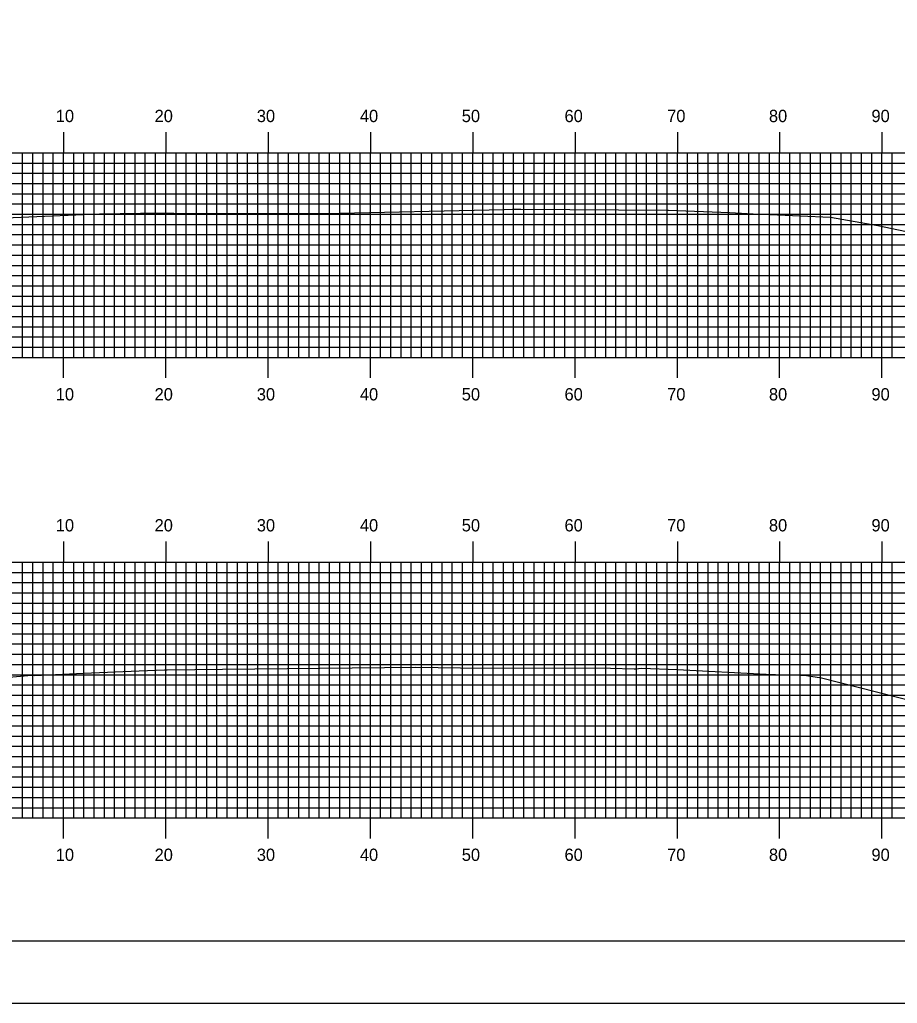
# Model space of a CAD drawing. Extents: x 855074 to 855418, y 366605 to 366825.
# Drawn here: x 855245.8 to 855331.6, y 366604.9 to 366701.1 of the extents above; entities that cross this region are included whole.
import ezdxf

# ---------------------------------------------------------------- set-up
doc = ezdxf.new("R2010")
doc.units = 0
for name, color, linetype in [('BORDER', 7, 'Continuous'), ('H_V ANNOTATION', 7, 'Continuous'), ('M_Roadway_Centerline', 7, 'Continuous'), ('MAJOR', 7, 'Continuous'), ('MINOR', 7, 'Continuous'), ('PLOT BOUNDARY', 7, 'Continuous'), ('S_Roadway_Centerline', 7, 'Continuous')]:
    doc.layers.add(name, color=color, linetype=linetype)

msp = doc.modelspace()

# ---------------------------------------------------------------- linework, layer by layer
at = {"layer": 'BORDER'}
msp.add_lwpolyline([(855090.469, 366611.055), (855410.469, 366611.055), (855410.469, 366821.055), (855090.469, 366821.055)], close=True, dxfattribs=at)
at = {"layer": 'MAJOR'}
for p, q in [((855250.069, 366690.059), (855250.069, 366688.055)), ((855260.069, 366690.059), (855260.069, 366688.055)), ((855270.069, 366690.059), (855270.069, 366688.055)), ((855280.069, 366690.059), (855280.069, 366688.055)), ((855290.069, 366690.059), (855290.069, 366688.055)), ((855300.069, 366690.059), (855300.069, 366688.055)), ((855310.069, 366690.059), (855310.069, 366688.055)), ((855320.069, 366690.059), (855320.069, 366688.055)), ((855330.069, 366690.059), (855330.069, 366688.055)), ((855100.069, 366688.055), (855380.069, 366688.055)), ((855100.069, 366688.055), (855380.069, 366688.055)), ((855250.069, 366668.055), (855250.069, 366688.055)), ((855260.069, 366668.055), (855260.069, 366688.055)), ((855270.069, 366668.055), (855270.069, 366688.055)), ((855280.069, 366668.055), (855280.069, 366688.055)), ((855290.069, 366668.055), (855290.069, 366688.055)), ((855300.069, 366668.055), (855300.069, 366688.055)), ((855310.069, 366668.055), (855310.069, 366688.055)), ((855320.069, 366668.055), (855320.069, 366688.055)), ((855330.069, 366668.055), (855330.069, 366688.055)), ((855100.069, 366683.055), (855380.069, 366683.055)), ((855100.069, 366678.055), (855380.069, 366678.055)), ((855100.069, 366673.055), (855380.069, 366673.055)), ((855100.069, 366668.055), (855380.069, 366668.055)), ((855100.069, 366668.055), (855380.069, 366668.055)), ((855250.069, 366666.051), (855250.069, 366668.055)), ((855260.069, 366666.051), (855260.069, 366668.055)), ((855270.069, 366666.051), (855270.069, 366668.055)), ((855280.069, 366666.051), (855280.069, 366668.055)), ((855290.069, 366666.051), (855290.069, 366668.055)), ((855300.069, 366666.051), (855300.069, 366668.055)), ((855310.069, 366666.051), (855310.069, 366668.055)), ((855320.069, 366666.051), (855320.069, 366668.055)), ((855330.069, 366666.051), (855330.069, 366668.055)), ((855250.069, 366650.059), (855250.069, 366648.055)), ((855260.069, 366650.059), (855260.069, 366648.055)), ((855270.069, 366650.059), (855270.069, 366648.055)), ((855280.069, 366650.059), (855280.069, 366648.055)), ((855290.069, 366650.059), (855290.069, 366648.055)), ((855300.069, 366650.059), (855300.069, 366648.055)), ((855310.069, 366650.059), (855310.069, 366648.055)), ((855320.069, 366650.059), (855320.069, 366648.055)), ((855330.069, 366650.059), (855330.069, 366648.055)), ((855100.069, 366648.055), (855380.069, 366648.055)), ((855100.069, 366648.055), (855380.069, 366648.055)), ((855250.069, 366623.055), (855250.069, 366648.055)), ((855260.069, 366623.055), (855260.069, 366648.055)), ((855270.069, 366623.055), (855270.069, 366648.055)), ((855280.069, 366623.055), (855280.069, 366648.055)), ((855290.069, 366623.055), (855290.069, 366648.055)), ((855300.069, 366623.055), (855300.069, 366648.055)), ((855310.069, 366623.055), (855310.069, 366648.055)), ((855320.069, 366623.055), (855320.069, 366648.055)), ((855330.069, 366623.055), (855330.069, 366648.055)), ((855100.069, 366643.055), (855380.069, 366643.055)), ((855100.069, 366638.055), (855380.069, 366638.055)), ((855100.069, 366633.055), (855380.069, 366633.055)), ((855100.069, 366628.055), (855380.069, 366628.055)), ((855100.069, 366623.055), (855380.069, 366623.055)), ((855100.069, 366623.055), (855380.069, 366623.055)), ((855250.069, 366621.051), (855250.069, 366623.055)), ((855260.069, 366621.051), (855260.069, 366623.055)), ((855270.069, 366621.051), (855270.069, 366623.055)), ((855280.069, 366621.051), (855280.069, 366623.055)), ((855290.069, 366621.051), (855290.069, 366623.055)), ((855300.069, 366621.051), (855300.069, 366623.055)), ((855310.069, 366621.051), (855310.069, 366623.055)), ((855320.069, 366621.051), (855320.069, 366623.055)), ((855330.069, 366621.051), (855330.069, 366623.055))]:
    msp.add_line(p, q, dxfattribs=at)
at = {"layer": 'MINOR'}
for p, q in [((855246.069, 366668.055), (855246.069, 366688.055)), ((855247.069, 366668.055), (855247.069, 366688.055)), ((855248.069, 366668.055), (855248.069, 366688.055)), ((855249.069, 366668.055), (855249.069, 366688.055)), ((855251.069, 366668.055), (855251.069, 366688.055)), ((855252.069, 366668.055), (855252.069, 366688.055)), ((855253.069, 366668.055), (855253.069, 366688.055)), ((855254.069, 366668.055), (855254.069, 366688.055)), ((855255.069, 366668.055), (855255.069, 366688.055)), ((855256.069, 366668.055), (855256.069, 366688.055)), ((855257.069, 366668.055), (855257.069, 366688.055)), ((855258.069, 366668.055), (855258.069, 366688.055)), ((855259.069, 366668.055), (855259.069, 366688.055)), ((855261.069, 366668.055), (855261.069, 366688.055)), ((855262.069, 366668.055), (855262.069, 366688.055)), ((855263.069, 366668.055), (855263.069, 366688.055)), ((855264.069, 366668.055), (855264.069, 366688.055)), ((855265.069, 366668.055), (855265.069, 366688.055)), ((855266.069, 366668.055), (855266.069, 366688.055)), ((855267.069, 366668.055), (855267.069, 366688.055)), ((855268.069, 366668.055), (855268.069, 366688.055)), ((855269.069, 366668.055), (855269.069, 366688.055)), ((855271.069, 366668.055), (855271.069, 366688.055)), ((855272.069, 366668.055), (855272.069, 366688.055)), ((855273.069, 366668.055), (855273.069, 366688.055)), ((855274.069, 366668.055), (855274.069, 366688.055)), ((855275.069, 366668.055), (855275.069, 366688.055)), ((855276.069, 366668.055), (855276.069, 366688.055)), ((855277.069, 366668.055), (855277.069, 366688.055)), ((855278.069, 366668.055), (855278.069, 366688.055)), ((855279.069, 366668.055), (855279.069, 366688.055)), ((855281.069, 366668.055), (855281.069, 366688.055)), ((855282.069, 366668.055), (855282.069, 366688.055)), ((855283.069, 366668.055), (855283.069, 366688.055)), ((855284.069, 366668.055), (855284.069, 366688.055)), ((855285.069, 366668.055), (855285.069, 366688.055)), ((855286.069, 366668.055), (855286.069, 366688.055)), ((855287.069, 366668.055), (855287.069, 366688.055)), ((855288.069, 366668.055), (855288.069, 366688.055)), ((855289.069, 366668.055), (855289.069, 366688.055)), ((855291.069, 366668.055), (855291.069, 366688.055)), ((855292.069, 366668.055), (855292.069, 366688.055)), ((855293.069, 366668.055), (855293.069, 366688.055)), ((855294.069, 366668.055), (855294.069, 366688.055)), ((855295.069, 366668.055), (855295.069, 366688.055)), ((855296.069, 366668.055), (855296.069, 366688.055)), ((855297.069, 366668.055), (855297.069, 366688.055)), ((855298.069, 366668.055), (855298.069, 366688.055)), ((855299.069, 366668.055), (855299.069, 366688.055)), ((855301.069, 366668.055), (855301.069, 366688.055)), ((855302.069, 366668.055), (855302.069, 366688.055)), ((855303.069, 366668.055), (855303.069, 366688.055)), ((855304.069, 366668.055), (855304.069, 366688.055)), ((855305.069, 366668.055), (855305.069, 366688.055)), ((855306.069, 366668.055), (855306.069, 366688.055)), ((855307.069, 366668.055), (855307.069, 366688.055)), ((855308.069, 366668.055), (855308.069, 366688.055)), ((855309.069, 366668.055), (855309.069, 366688.055)), ((855311.069, 366668.055), (855311.069, 366688.055)), ((855312.069, 366668.055), (855312.069, 366688.055)), ((855313.069, 366668.055), (855313.069, 366688.055)), ((855314.069, 366668.055), (855314.069, 366688.055)), ((855315.069, 366668.055), (855315.069, 366688.055)), ((855316.069, 366668.055), (855316.069, 366688.055)), ((855317.069, 366668.055), (855317.069, 366688.055)), ((855318.069, 366668.055), (855318.069, 366688.055)), ((855319.069, 366668.055), (855319.069, 366688.055)), ((855321.069, 366668.055), (855321.069, 366688.055)), ((855322.069, 366668.055), (855322.069, 366688.055)), ((855323.069, 366668.055), (855323.069, 366688.055)), ((855324.069, 366668.055), (855324.069, 366688.055)), ((855325.069, 366668.055), (855325.069, 366688.055)), ((855326.069, 366668.055), (855326.069, 366688.055)), ((855327.069, 366668.055), (855327.069, 366688.055)), ((855328.069, 366668.055), (855328.069, 366688.055)), ((855329.069, 366668.055), (855329.069, 366688.055)), ((855331.069, 366668.055), (855331.069, 366688.055)), ((855100.069, 366687.055), (855380.069, 366687.055)), ((855100.069, 366686.055), (855380.069, 366686.055)), ((855100.069, 366685.055), (855380.069, 366685.055)), ((855100.069, 366684.055), (855380.069, 366684.055)), ((855100.069, 366682.055), (855380.069, 366682.055)), ((855100.069, 366681.055), (855380.069, 366681.055)), ((855100.069, 366680.055), (855380.069, 366680.055)), ((855100.069, 366679.055), (855380.069, 366679.055)), ((855100.069, 366677.055), (855380.069, 366677.055)), ((855100.069, 366676.055), (855380.069, 366676.055)), ((855100.069, 366675.055), (855380.069, 366675.055)), ((855100.069, 366674.055), (855380.069, 366674.055)), ((855100.069, 366672.055), (855380.069, 366672.055)), ((855100.069, 366671.055), (855380.069, 366671.055)), ((855100.069, 366670.055), (855380.069, 366670.055)), ((855100.069, 366669.055), (855380.069, 366669.055)), ((855246.069, 366623.055), (855246.069, 366648.055)), ((855247.069, 366623.055), (855247.069, 366648.055)), ((855248.069, 366623.055), (855248.069, 366648.055)), ((855249.069, 366623.055), (855249.069, 366648.055)), ((855251.069, 366623.055), (855251.069, 366648.055)), ((855252.069, 366623.055), (855252.069, 366648.055)), ((855253.069, 366623.055), (855253.069, 366648.055)), ((855254.069, 366623.055), (855254.069, 366648.055)), ((855255.069, 366623.055), (855255.069, 366648.055)), ((855256.069, 366623.055), (855256.069, 366648.055)), ((855257.069, 366623.055), (855257.069, 366648.055)), ((855258.069, 366623.055), (855258.069, 366648.055)), ((855259.069, 366623.055), (855259.069, 366648.055)), ((855261.069, 366623.055), (855261.069, 366648.055)), ((855262.069, 366623.055), (855262.069, 366648.055)), ((855263.069, 366623.055), (855263.069, 366648.055)), ((855264.069, 366623.055), (855264.069, 366648.055)), ((855265.069, 366623.055), (855265.069, 366648.055)), ((855266.069, 366623.055), (855266.069, 366648.055)), ((855267.069, 366623.055), (855267.069, 366648.055)), ((855268.069, 366623.055), (855268.069, 366648.055)), ((855269.069, 366623.055), (855269.069, 366648.055)), ((855271.069, 366623.055), (855271.069, 366648.055)), ((855272.069, 366623.055), (855272.069, 366648.055)), ((855273.069, 366623.055), (855273.069, 366648.055)), ((855274.069, 366623.055), (855274.069, 366648.055)), ((855275.069, 366623.055), (855275.069, 366648.055)), ((855276.069, 366623.055), (855276.069, 366648.055)), ((855277.069, 366623.055), (855277.069, 366648.055)), ((855278.069, 366623.055), (855278.069, 366648.055)), ((855279.069, 366623.055), (855279.069, 366648.055)), ((855281.069, 366623.055), (855281.069, 366648.055)), ((855282.069, 366623.055), (855282.069, 366648.055)), ((855283.069, 366623.055), (855283.069, 366648.055)), ((855284.069, 366623.055), (855284.069, 366648.055)), ((855285.069, 366623.055), (855285.069, 366648.055)), ((855286.069, 366623.055), (855286.069, 366648.055)), ((855287.069, 366623.055), (855287.069, 366648.055)), ((855288.069, 366623.055), (855288.069, 366648.055)), ((855289.069, 366623.055), (855289.069, 366648.055)), ((855291.069, 366623.055), (855291.069, 366648.055)), ((855292.069, 366623.055), (855292.069, 366648.055)), ((855293.069, 366623.055), (855293.069, 366648.055)), ((855294.069, 366623.055), (855294.069, 366648.055)), ((855295.069, 366623.055), (855295.069, 366648.055)), ((855296.069, 366623.055), (855296.069, 366648.055)), ((855297.069, 366623.055), (855297.069, 366648.055)), ((855298.069, 366623.055), (855298.069, 366648.055)), ((855299.069, 366623.055), (855299.069, 366648.055)), ((855301.069, 366623.055), (855301.069, 366648.055)), ((855302.069, 366623.055), (855302.069, 366648.055)), ((855303.069, 366623.055), (855303.069, 366648.055)), ((855304.069, 366623.055), (855304.069, 366648.055)), ((855305.069, 366623.055), (855305.069, 366648.055)), ((855306.069, 366623.055), (855306.069, 366648.055)), ((855307.069, 366623.055), (855307.069, 366648.055)), ((855308.069, 366623.055), (855308.069, 366648.055)), ((855309.069, 366623.055), (855309.069, 366648.055)), ((855311.069, 366623.055), (855311.069, 366648.055)), ((855312.069, 366623.055), (855312.069, 366648.055)), ((855313.069, 366623.055), (855313.069, 366648.055)), ((855314.069, 366623.055), (855314.069, 366648.055)), ((855315.069, 366623.055), (855315.069, 366648.055)), ((855316.069, 366623.055), (855316.069, 366648.055)), ((855317.069, 366623.055), (855317.069, 366648.055)), ((855318.069, 366623.055), (855318.069, 366648.055)), ((855319.069, 366623.055), (855319.069, 366648.055)), ((855321.069, 366623.055), (855321.069, 366648.055)), ((855322.069, 366623.055), (855322.069, 366648.055)), ((855323.069, 366623.055), (855323.069, 366648.055)), ((855324.069, 366623.055), (855324.069, 366648.055)), ((855325.069, 366623.055), (855325.069, 366648.055)), ((855326.069, 366623.055), (855326.069, 366648.055)), ((855327.069, 366623.055), (855327.069, 366648.055)), ((855328.069, 366623.055), (855328.069, 366648.055)), ((855329.069, 366623.055), (855329.069, 366648.055)), ((855331.069, 366623.055), (855331.069, 366648.055)), ((855100.069, 366647.055), (855380.069, 366647.055)), ((855100.069, 366646.055), (855380.069, 366646.055)), ((855100.069, 366645.055), (855380.069, 366645.055)), ((855100.069, 366644.055), (855380.069, 366644.055)), ((855100.069, 366642.055), (855380.069, 366642.055)), ((855100.069, 366641.055), (855380.069, 366641.055)), ((855100.069, 366640.055), (855380.069, 366640.055)), ((855100.069, 366639.055), (855380.069, 366639.055)), ((855100.069, 366637.055), (855380.069, 366637.055)), ((855100.069, 366636.055), (855380.069, 366636.055)), ((855100.069, 366635.055), (855380.069, 366635.055)), ((855100.069, 366634.055), (855380.069, 366634.055)), ((855100.069, 366632.055), (855380.069, 366632.055)), ((855100.069, 366631.055), (855380.069, 366631.055)), ((855100.069, 366630.055), (855380.069, 366630.055)), ((855100.069, 366629.055), (855380.069, 366629.055)), ((855100.069, 366627.055), (855380.069, 366627.055)), ((855100.069, 366626.055), (855380.069, 366626.055)), ((855100.069, 366625.055), (855380.069, 366625.055)), ((855100.069, 366624.055), (855380.069, 366624.055))]:
    msp.add_line(p, q, dxfattribs=at)
at = {"layer": 'PLOT BOUNDARY'}
msp.add_lwpolyline([(855074.283, 366604.937), (855414.283, 366604.937), (855414.283, 366824.937), (855074.283, 366824.937)], close=True, dxfattribs=at)
at = {"layer": 'S_Roadway_Centerline'}
for points in [[(855242.055, 366681.596), (855250.542, 366681.959), (855253.591, 366682.103), (855257.609, 366682.147), (855258.058, 366682.159), (855260.86, 366682.158), (855275.585, 366682.124), (855293.136, 366682.51), (855293.952, 366682.538), (855294.383, 366682.551), (855294.759, 366682.541), (855309.102, 366682.437), (855309.202, 366682.459), (855315.175, 366682.219), (855318.065, 366682.069), (855319.114, 366682.022), (855325.035, 366681.758), (855329.673, 366680.937), (855333.694, 366680.1)], [(855242.18, 366636.596), (855246.931, 366636.992), (855247.227, 366636.978), (855252.038, 366637.197), (855257.48, 366637.444), (855259.929, 366637.536), (855260.212, 366637.525), (855265.605, 366637.603), (855281.453, 366637.754), (855284.521, 366637.773), (855288.877, 366637.739), (855303.528, 366637.705), (855305.847, 366637.639), (855305.963, 366637.633), (855306.575, 366637.683), (855310.059, 366637.554), (855318.751, 366637.109), (855319.662, 366637.07), (855321.427, 366637.027), (855322.699, 366636.98), (855324.149, 366636.747), (855335.174, 366633.949)]]:
    msp.add_lwpolyline(points, dxfattribs=at)

# ---------------------------------------------------------------- texts
at = {"layer": 'H_V ANNOTATION'}
for s, p in [('10', (855249.32, 366691.055)), ('20', (855258.977, 366691.055)), ('30', (855268.967, 366691.055)), ('40', (855279.042, 366691.055)), ('50', (855288.999, 366691.055)), ('60', (855299.042, 366691.055)), ('70', (855309.074, 366691.055)), ('80', (855319.02, 366691.055)), ('90', (855329.042, 366691.055)), ('10', (855249.32, 366663.855)), ('20', (855258.977, 366663.855)), ('30', (855268.967, 366663.855)), ('40', (855279.042, 366663.855)), ('50', (855288.999, 366663.855)), ('60', (855299.042, 366663.855)), ('70', (855309.074, 366663.855)), ('80', (855319.02, 366663.855)), ('90', (855329.042, 366663.855)), ('10', (855249.32, 366651.055)), ('20', (855258.977, 366651.055)), ('30', (855268.967, 366651.055)), ('40', (855279.042, 366651.055)), ('50', (855288.999, 366651.055)), ('60', (855299.042, 366651.055)), ('70', (855309.074, 366651.055)), ('80', (855319.02, 366651.055)), ('90', (855329.042, 366651.055)), ('10', (855249.32, 366618.855)), ('20', (855258.977, 366618.855)), ('30', (855268.967, 366618.855)), ('40', (855279.042, 366618.855)), ('50', (855288.999, 366618.855)), ('60', (855299.042, 366618.855)), ('70', (855309.074, 366618.855)), ('80', (855319.02, 366618.855)), ('90', (855329.042, 366618.855))]:
    msp.add_text(s, height=1.2, dxfattribs=at).set_placement(p)
at = {"layer": 'M_Roadway_Centerline'}
for s, p in [('C', (855253.586, 366682.103)), ('L', (855253.591, 366682.096)), ('C', (855309.197, 366682.459)), ('L', (855309.202, 366682.452)), ('C', (855259.924, 366637.536)), ('L', (855259.929, 366637.528)), ('C', (855306.57, 366637.683)), ('L', (855306.575, 366637.675))]:
    msp.add_text(s, height=0.0146, dxfattribs=at).set_placement(p)

doc.saveas('drawing.dxf')
